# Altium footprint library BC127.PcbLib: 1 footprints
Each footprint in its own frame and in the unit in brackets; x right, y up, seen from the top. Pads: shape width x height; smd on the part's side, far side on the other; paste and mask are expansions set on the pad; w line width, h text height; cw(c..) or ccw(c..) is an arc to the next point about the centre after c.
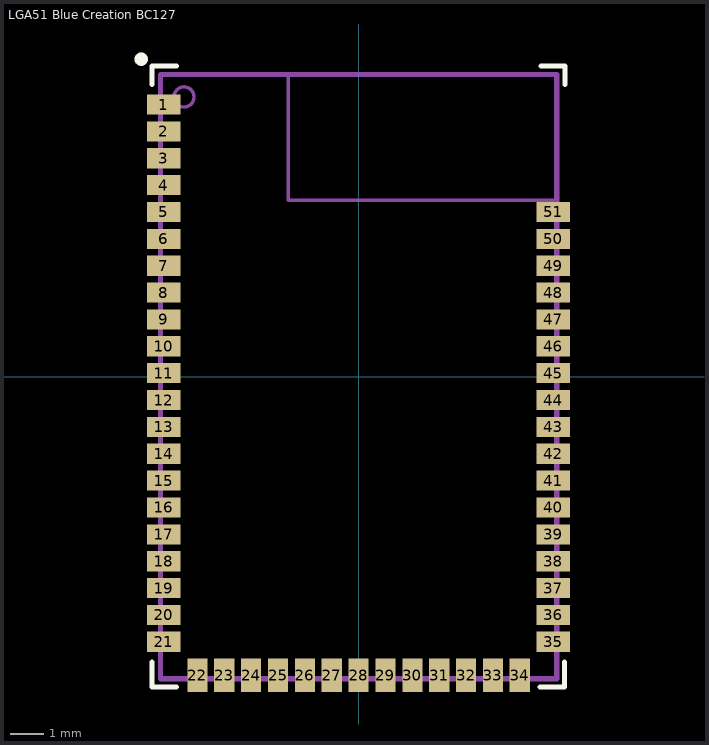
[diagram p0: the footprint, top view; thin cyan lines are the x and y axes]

## LGA51 Blue Creation BC127 [mm] "LGA, 51-Leads, Body 18x11.8mm, Pitch 0.8mm"
height 2.4
pads (51):
  rect 1x0.6 smd paste+0 mask+0.05: 1(-5.8,8.1) 2(-5.8,7.3) 3(-5.8,6.5) 4(-5.8,5.7) 5(-5.8,4.9) 6(-5.8,4.1) 7(-5.8,3.3) 8(-5.8,2.5) 9(-5.8,1.7) 10(-5.8,0.9) 11(-5.8,0.1) 12(-5.8,-0.7) 13(-5.8,-1.5) 14(-5.8,-2.3) 15(-5.8,-3.1) 16(-5.8,-3.9) 17(-5.8,-4.7) 18(-5.8,-5.5) 19(-5.8,-6.3) 20(-5.8,-7.1) 21(-5.8,-7.9) 35(5.8,-7.9) 36(5.8,-7.1) 37(5.8,-6.3) 38(5.8,-5.5) 39(5.8,-4.7) 40(5.8,-3.9) 41(5.8,-3.1) 42(5.8,-2.3) 43(5.8,-1.5) 44(5.8,-0.7) 45(5.8,0.1) 46(5.8,0.9) 47(5.8,1.7) 48(5.8,2.5) 49(5.8,3.3) 50(5.8,4.1) 51(5.8,4.9)
  rect 0.6x1 smd paste+0 mask+0.05: 22(-4.8,-8.9) 23(-4,-8.9) 24(-3.2,-8.9) 25(-2.4,-8.9) 26(-1.6,-8.9) 27(-0.8,-8.9) 28(0,-8.9) 29(0.8,-8.9) 30(1.6,-8.9) 31(2.4,-8.9) 32(3.2,-8.9) 33(4,-8.9) 34(4.8,-8.9)
Top Overlay:
  circle w0.2: c-6.475,9.45 r0.1
  lines w0.15: -6.15,-8.5 -6.15,-9.25 -5.425,-9.25 ; -6.15,8.7 -6.15,9.25 -5.425,9.25 ; 5.4,-9.25 6.125,-9.25 6.125,-8.5 ; 5.425,9.25 6.15,9.25 6.15,8.7
Mechanical 4:
  circle w0.1: c-5.2,8.325 r0.3
  lines w0.1: -2.1,9 -2.1,5.25 5.9,5.25
  lines w0.15: -5.9,-9 5.9,-9 5.9,9 -5.9,9 -5.9,-9
  text "GND Cut Out" at -1.1,6.5 h0.6
  text ".Designator" at 0,0 h0.6
3D body: height 2.4, standoff 0, extent -5.9,-9 5.9,9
